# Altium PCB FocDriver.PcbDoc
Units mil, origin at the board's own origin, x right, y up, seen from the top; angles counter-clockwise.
Board outline 2410.04 x 1811.02 mil, 2 copper layers (Top Layer, Bottom Layer); 20 components, 19 nets, 98 pads, 41 vias.
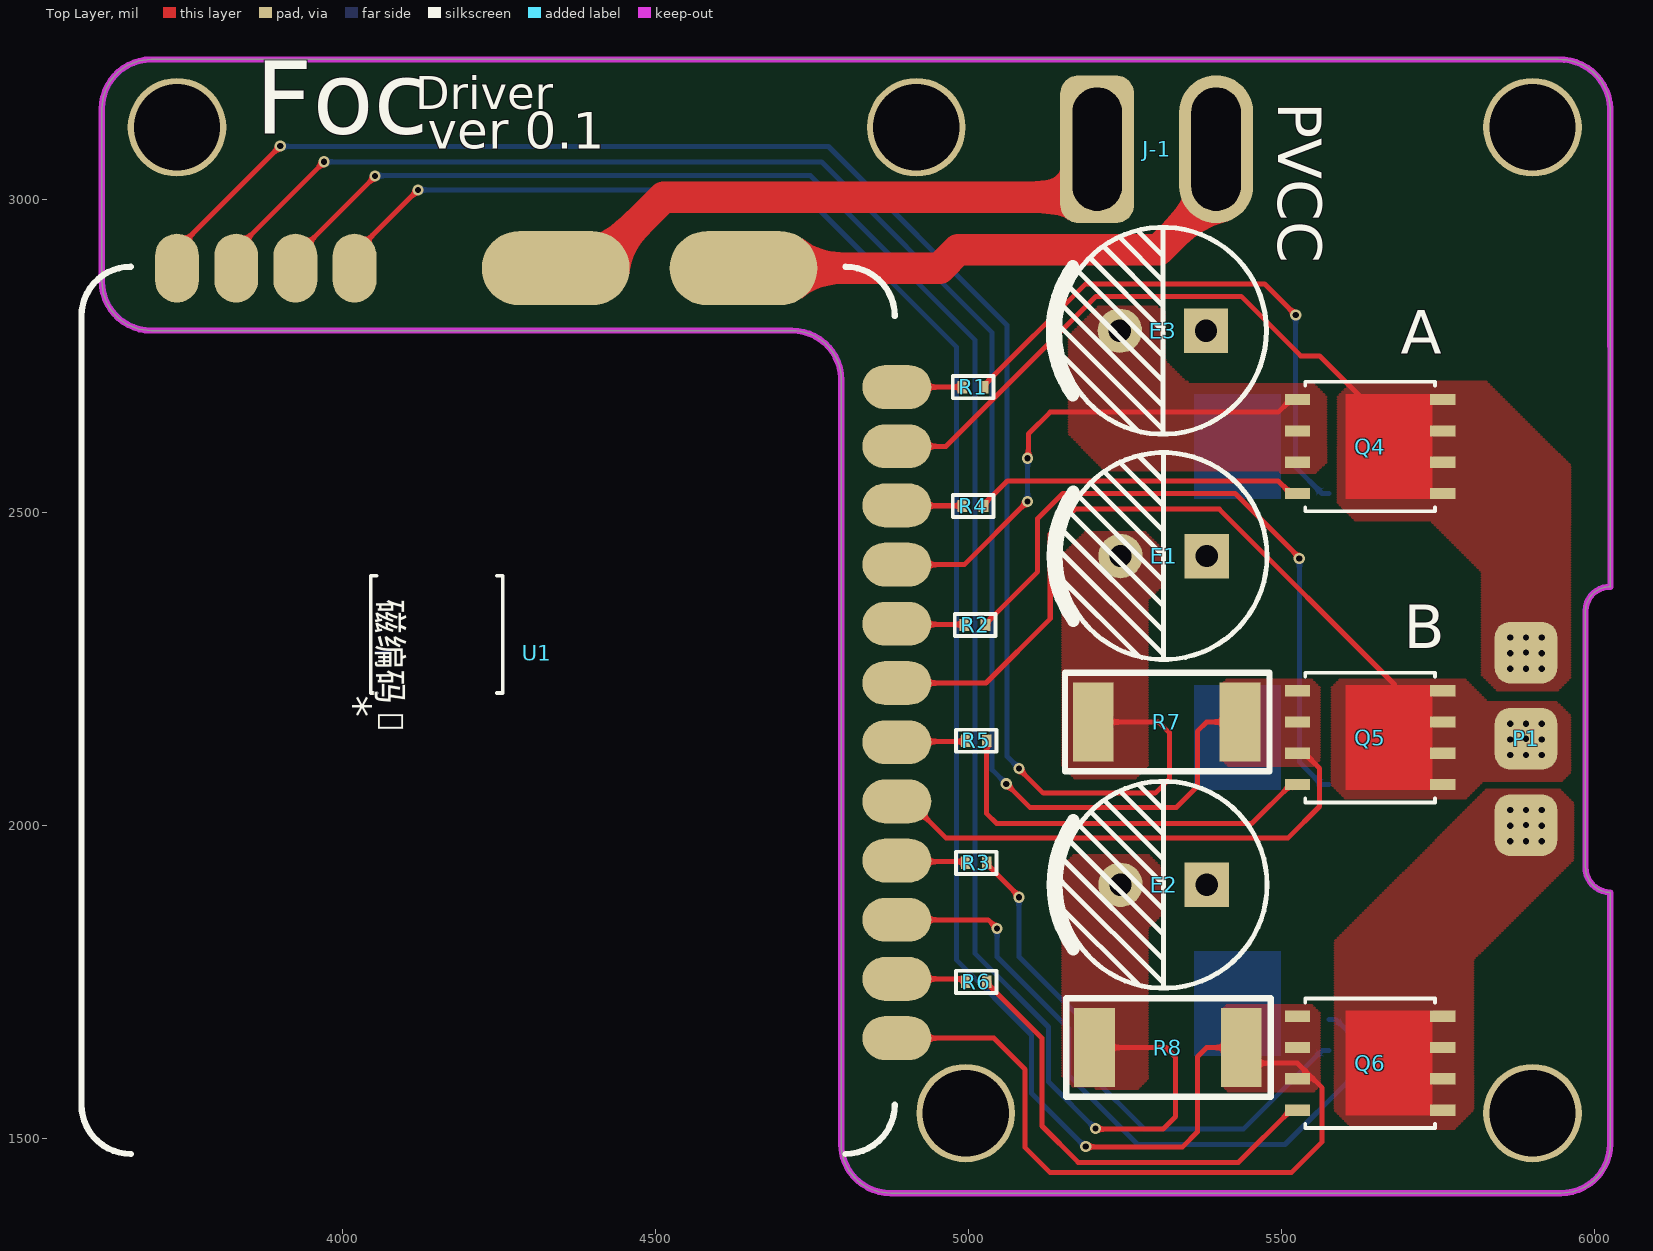
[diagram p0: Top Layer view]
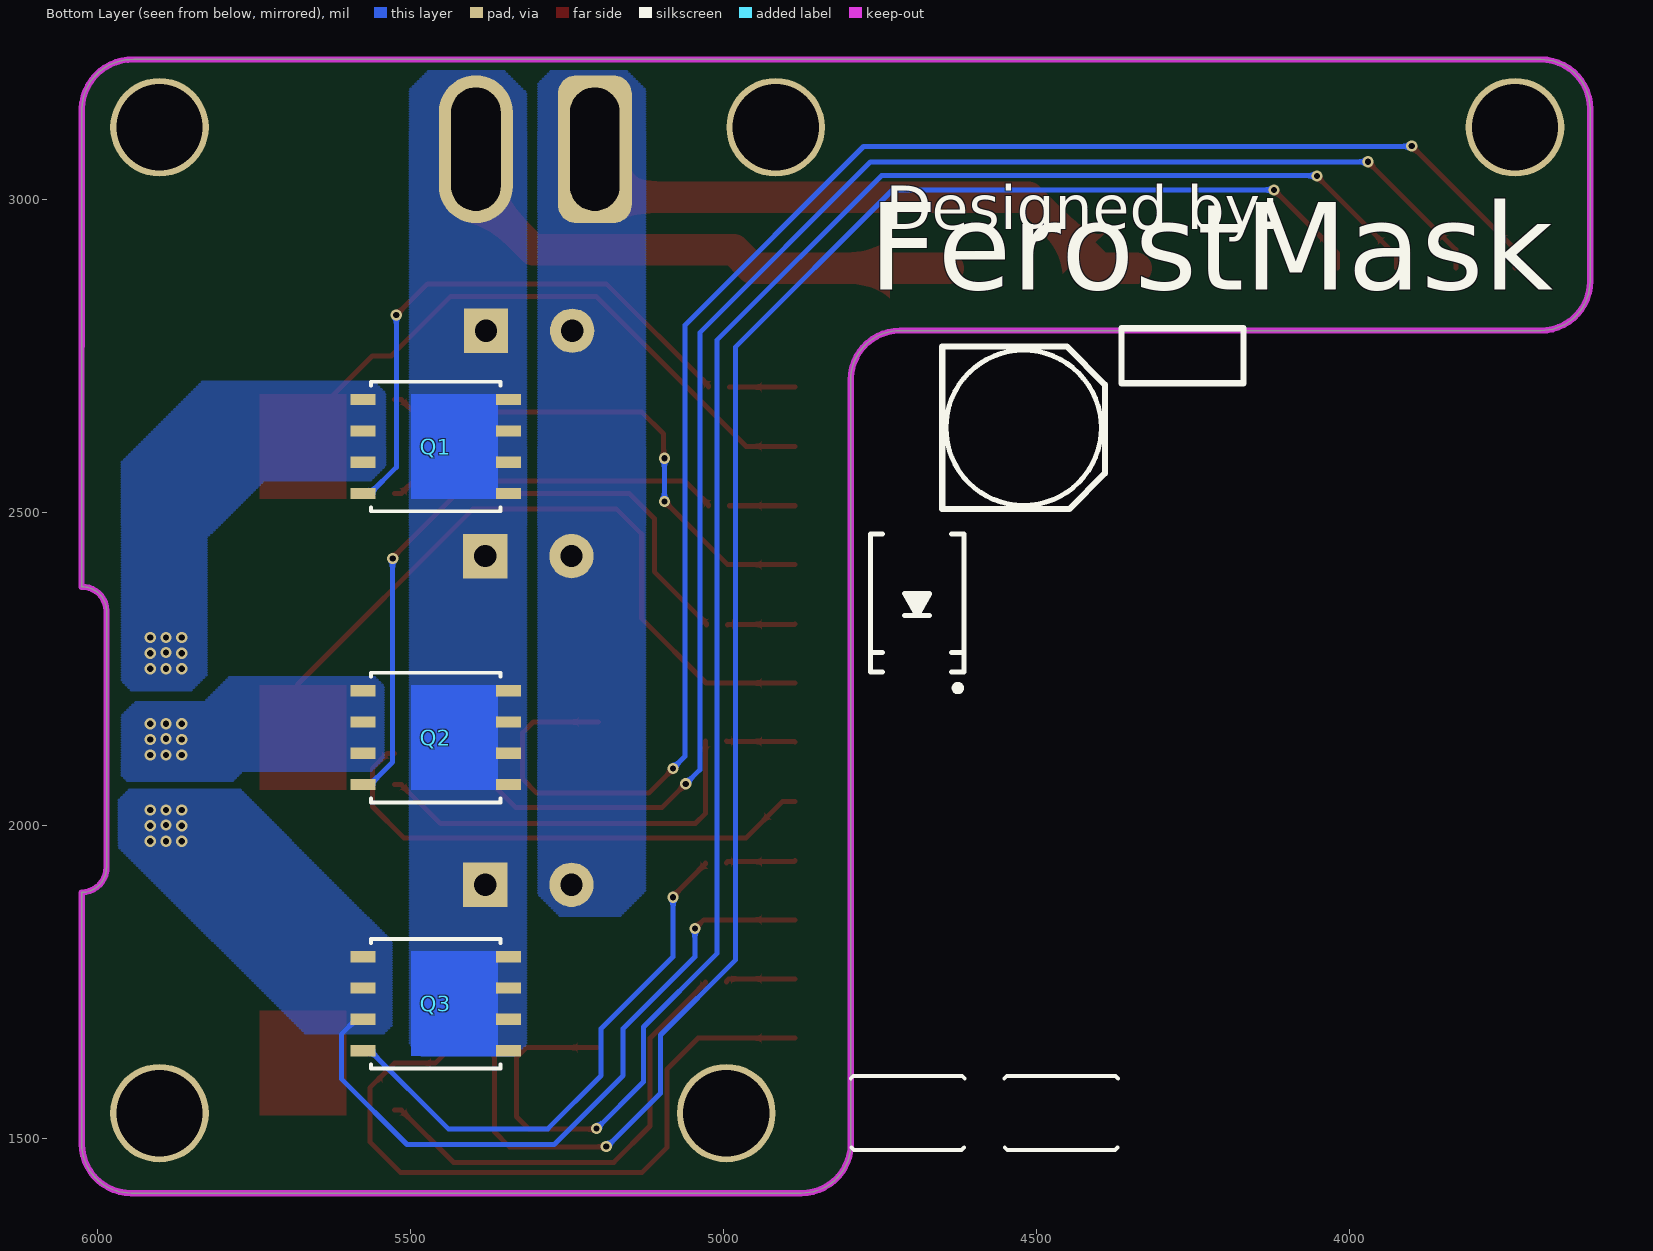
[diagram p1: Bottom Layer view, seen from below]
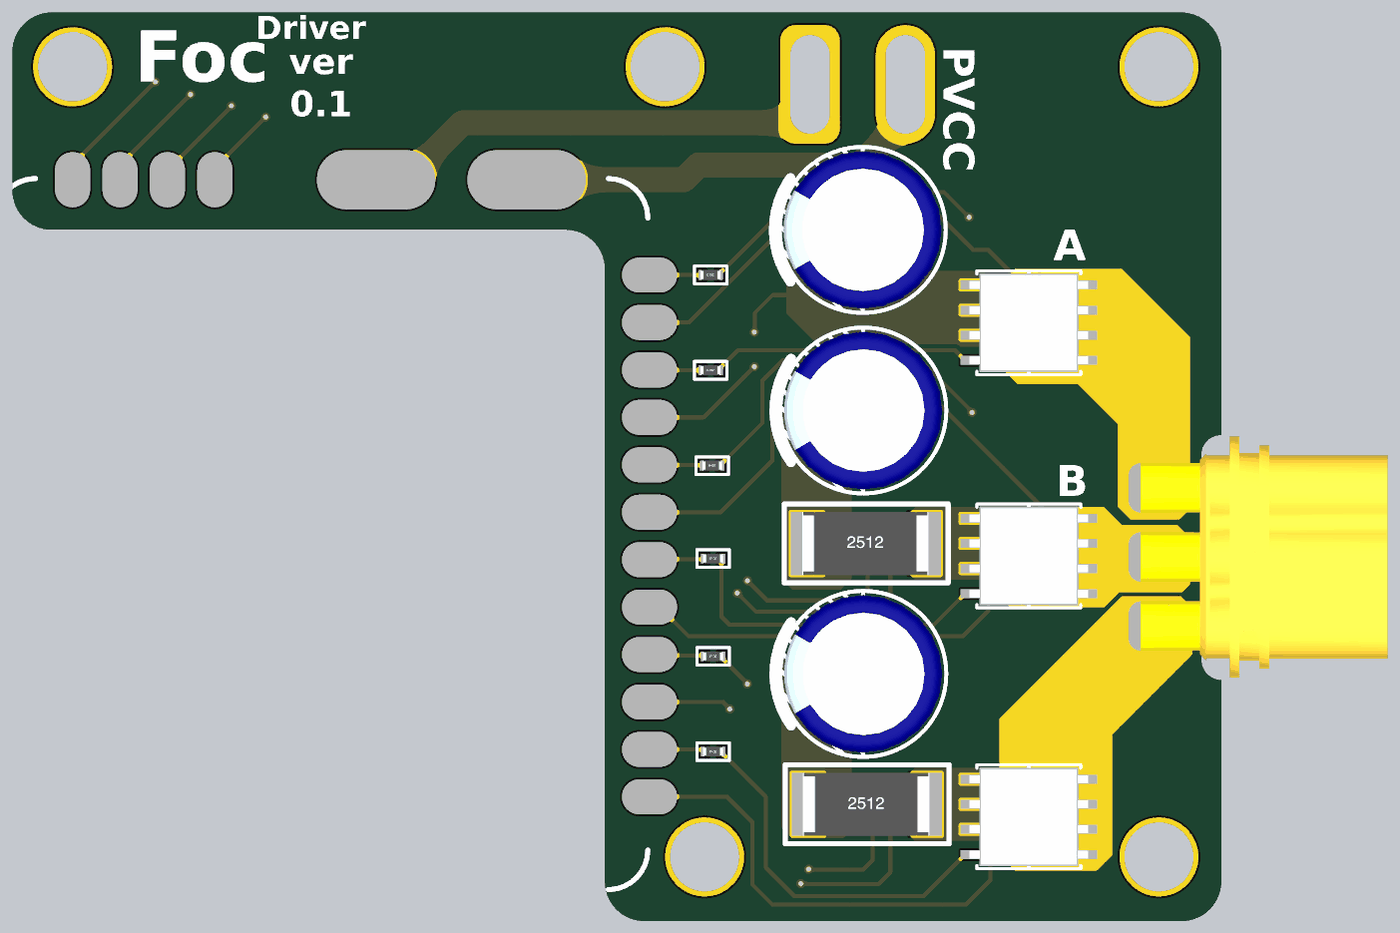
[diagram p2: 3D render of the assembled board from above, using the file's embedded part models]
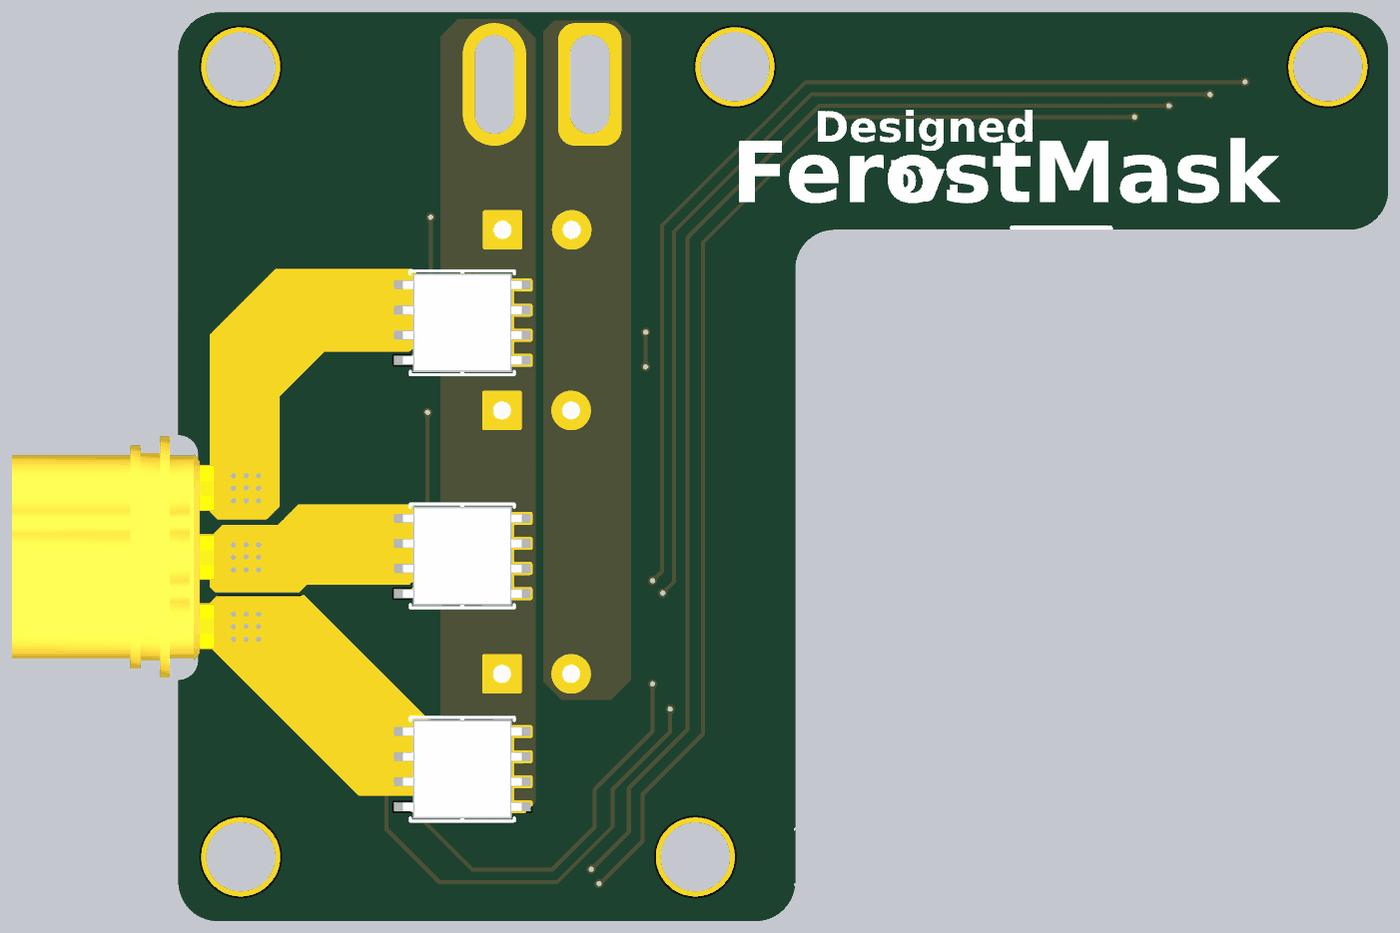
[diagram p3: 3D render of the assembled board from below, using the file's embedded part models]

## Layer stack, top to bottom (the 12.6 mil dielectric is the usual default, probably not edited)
Top Solder: solder mask 0.4, Solder Resist, Dk 3.5
Top Layer: signal copper 1.4
Dielectric 1: dielectric 12.6, FR-4, Dk 4.8
Bottom Layer: signal copper 1.4
Bottom Solder: solder mask 0.4, Solder Resist, Dk 3.5

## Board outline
4717.36,2790.31 cw(c4717.36,2711.57) 4796.1,2711.57 4796.1,1491.1 ccw(c4874.84,1491.1) 4874.84,1412.36 5945.71,1412.36 ccw(c5945.71,1491.1) 6024.45,1491.1 6024.45,1892.68 cw(c6025.22,1932.89) 5985,1933.66 5985,2343.11 cw(c6023.94,2342.01) 6025.04,2380.94 6024.97,2380.95 6024.5,3144.77 ccw(c5943.57,3142.46) 5941.26,3223.39 3693.74,3223.39 ccw(c3693.74,3144.65) 3615,3144.65 3615,2869.06 ccw(c3693.74,2869.06) 3693.74,2790.31

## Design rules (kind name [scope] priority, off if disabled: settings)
Clearance [All] p1: gap=8 ignorepadtopadclearanceinfootprint=TRUE
PlaneConnect [All] p1: planeconnectstyle=Direct reliefexpansion=20 reliefentries=4 reliefconductorwidth=10 reliefairgap=10
PolygonConnect [All] p1: connectstyle=Direct reliefconductorwidth=30 reliefentries=4 polygonreliefangle="90 Angle" airgapwidth=10
RoomDefinition Main [InComponentClass('Main')] p1: confinementstyle=ConfineIn formatcopy=TRUE lockcomponents=FALSE outline 0,0 2000,0 2000,1000 0,1000
RoutingVias [All] p1: holewidth=12 width=24 viastyle="Through Hole" minholewidth=12 minwidth=24 maxholewidth=12 maxwidth=24
SolderMaskExpansion [All] p1: expansion=4 istentingtop=FALSE
Width [All] p1: maxlimit=200 minlimit=6 preferedwidth=6
29 further rules are at their usual default settings.

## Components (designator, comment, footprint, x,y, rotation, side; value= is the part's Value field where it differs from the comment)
E1 "220uF/35V" "CAP 3.5*8*11.5" 5311.1,2430 r180 top
E2 "220uF/35V" "CAP 3.5*8*11.5" 5311.1,1905 r180 top
E3 "220uF/35V" "CAP 3.5*8*11.5" 5310,2790 r180 top
J-1 "Conects" connecter-PWR_vertical 5395,3080 r0 top
P1 "电机接插件-3P" AMASS-MR30-M 5890,2138.11 r90 top
Q1 "2SK3615" "SOP Advance_TOS" 5459,2605 r180 bottom
Q2 "2SK3615" "SOP Advance_TOS" 5459,2140 r180 bottom
Q3 "2SK3615" "SOP Advance_TOS" 5459,1715 r180 bottom
Q4 "2SK3615" "SOP Advance_TOS" 5641,2605 r0 top
Q5 "2SK3615" "SOP Advance_TOS" 5641,2140 r0 top
Q6 "2SK3615" "SOP Advance_TOS" 5641,1620 r0 top
R1 "2.2R" R0402_L 5006.73,2700 r0 top
R2 "2.2R" R0402_L 5010,2320 r0 top
R3 "2.2R" R0402_L 5011.73,1940 r0 top
R4 "2.2R" R0402_L 5006.73,2510 r0 top
R5 "2.2R" R0402_L 5011.73,2135 r0 top
R6 "2.2R" R0402_L 5011.73,1750 r0 top
R7 "0.01R" R2512_L 5315,2165 r0 top
R8 "0.01R" R2512_L 5316.89,1645 r0 top
U1 "FocLogic" FocLogic 4340,2890 r270 top

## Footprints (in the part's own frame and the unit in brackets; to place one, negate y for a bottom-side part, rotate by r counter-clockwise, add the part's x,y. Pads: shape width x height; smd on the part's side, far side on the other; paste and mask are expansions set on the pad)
AMASS-MR30-M [mm]
  rrect50% 2.5x2.54 smd: 1(-3.5,0) 2(0,0) 3(3.5,0)
  body extent -6.1,-11.84 6.1,0.66, height 2.6
"CAP 3.5*8*11.5" [mm] "脚距3.5mm直径8mm高度11.5mm"
  rect 1.8x1.8 hole 0.9: 1(-1.75,0)
  round 1.8 hole 0.9: 2(1.75,0)
  silkscreen extent -4.2,-4.2 4.5,4.2, body extent -4,-4 4.01,4, height 11.53
connecter-PWR_vertical [mm]
  oval 3x6 hole 5 slot 2 at 0 deg: 1(0,0)
  rrect50% 3x6 hole 5 slot 2 at 0 deg: 2(-4.826,0)
FocLogic [mil]
  oval 70x110 smd: 1(1230,545) 2(1135.45,545) 3(1040.91,545) 4(946.36,545) 5(851.82,545) 6(757.27,545) 7(662.73,545) 8(568.18,545) 9(473.64,545) 10(379.09,545) 11(284.55,545)
  oval 70x110 smd mask+4: 12(190,545)
  oval 118.11x236.22 smd: 13(0,300) 14(0,0)
  oval 110x70 smd: 15(0,-321.36) 16(0,-415.91) 17(0,-510.45) 18(0,-605)
  silkscreen extent -2,-758 1415,542
R0402_L [mm] "1/16W贴片电阻"
  rect 0.4x0.5 smd: 1(-0.425,0) 2(0.425,0)
  silkscreen extent -0.82,-0.45 0.83,0.45, body extent -0.5,-0.25 0.5,0.25, height 0.3
R2512_L [mm] "1W贴片电阻            联系卖家 免费查找封装"
  rect 1.65x3.2 smd: 1(-2.95,0) 2(3,0)
  silkscreen extent -4.1,-2 4.2,2, body extent -3.2,-1.6 3.2,1.6, height 0.55
"SOP Advance_TOS" [mil]
  rect 40x18 smd: 1(-116,-75) 2(116,-75) 2(116,-25) 2(116,25) 2(116,75) 3(-116,-25) 3(-116,25) 3(-116,75)
  Top Layer region: -39,83.5 99,83.5 99,-83.5 -39,-83.5
  silkscreen extent -104,-104 104,104, body extent -118,-104 118,104, height 37

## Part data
E1 E2 E3: library part C-CM, "电容"
J-1 P1: "插接件"
Q1 Q2 Q3 Q4 Q5 Q6: library part MOSFETN, "MOSFET"
R1 R2 R3 R4 R5 R6 R7 R8: library part R, "电阻"
U1: "PCBModel"

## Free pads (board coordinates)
  round 157.48 hole 137.8: 8(3735,3115) 8(4916.1,3115) 8(4994.84,1540.2) 8(5900.35,1540.2) 8(5900.35,3115)

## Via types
v1: diameter 18, hole 10, Top Layer to Bottom Layer, tented both sides, 41 vias

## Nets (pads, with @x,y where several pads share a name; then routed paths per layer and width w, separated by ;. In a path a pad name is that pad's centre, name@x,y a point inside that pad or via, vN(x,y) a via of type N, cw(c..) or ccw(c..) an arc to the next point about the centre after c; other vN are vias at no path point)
GH_A: R1.1 U1.12 | length 105
  Top Layer w8: U1.12 R1.1
GH_B: R2.1 U1.8 | length 109
  Top Layer w8: U1.8 4885.91,2320.91 4992.36,2320.91 R2.1
GH_C: R3.1 U1.4 | length 111.5
  Top Layer w8: U1.4 4886.82,1941.82 4993.18,1941.82 R3.1
GL_A: R4.1 U1.10 | length 105.4
  Top Layer w8: U1.10 4885.45,2510.45 4989.55,2510.45 R4.1
GL_B: R5.1 U1.6 | length 110.9
  Top Layer w8: U1.6 4886.14,2133.86 4993.86,2133.86 R5.1
GL_C: R6.1 U1.2 | length 112.3
  Top Layer w8: U1.2 4991.13,1754.55 4995,1750.67 R6.1
GND: E1.2 E2.2 E3.2 J-1.2 Q4.3 R7.1 R8.1 U1.9 U1.14 U1.16 U1.18 | length 7480.3
  Top Layer w8: U1.18 3735,2920 v1(3900,3085) ; U1.16 3924.09,2909.09 v1@4050,3035 ; U1.9 4992.65,2416.36 5093.4,2517.12 v1(5093.83,2517.12) ; v1@5079.76,2090.42 5118.82,2051.35 5297.58,2051.35 5320.2,2073.97 5320.2,2147.92 5303.11,2165 R7.1 ; v1(5093.75,2586.26) 5095,2587.51 5095,2625 5130,2660 5494,2660 5514,2680 Q4.3@5525,2680 ; R8.1 5315,1645 5330,1630 5330,1534.64 5309.99,1514.62 v1@5201.25,1514.62
  Top Layer w50: U1.14 4399.06,2890 4512.31,3003.26 5171.29,3003.26 5205,3036.97 J-1.2
  Bottom Layer w8: v1@3899.98,3084.72 3900.32,3084.38 4775.62,3084.38 5061,2799 5061,2110.1 v1(5080.22,2090.87) ; v1@4051.44,3037.71 4747.15,3037.71 5010,2774.86 5010,1795 5127.3,1677.7 5127.3,1590.21 v1@5202.91,1514.6 ; v1(5093.83,2517.12) 5093.83,2584.99 v1@5094.64,2585.8
  other v1: 5202.2,1515.61 4051.44,3037.38
NetQ1_1: Q1.1 R1.2 | length 902.3
  Top Layer w8: R1.2 5023.46,2701.97 5186.5,2865 5472.31,2865 v1(5522.06,2815.24)
  Bottom Layer w8: v1(5522.06,2815.24) 5522.06,2571.94 5564,2530 Q1.1
NetQ2_1: Q2.1 R2.2 | length 1073.3
  Top Layer w8: R2.2 5026.73,2321.97 5110,2405.24 5110,2490 5150,2530 5425.49,2530 v1@5531.41,2424.08
  Bottom Layer w8: v1(5527.83,2426.01) 5528.15,2425.69 5528.15,2100.85 5564,2065 Q2.1
NetQ3_1: Q3.1 R3.2 | length 876
  Top Layer w8: R3.2 5028.46,1938.03 5080,1886.5 v1(5080,1885)
  Bottom Layer w8: v1(5080,1885) 5080,1790 5195,1675 5195,1600 5280,1515 5439,1515 5564,1640 Q3.1
NetQ4_1: Q4.1 R4.2 | length 527.5
  Top Layer w8: R4.2 5023.46,2511.97 5061.5,2550 5494,2550 5514,2530 Q4.1
NetQ5_1: Q5.1 R5.2 | length 645.3
  Top Layer w8: R5.2 5028.46,2018.55 5044.3,2002.72 5451.72,2002.72 5514,2065 Q5.1
NetQ6_1: Q6.1 R6.2 | length 733.7
  Top Layer w8: R6.2 5028.46,1748.03 5116.69,1659.81 5116.69,1519.66 5174.65,1461.7 5430.7,1461.7 5514,1545 Q6.1
SH_A: P1.3 Q1.3 Q4.2 U1.11 | length 960
  Top Layer w8: U1.11 4963.61,2605.45 5203.15,2845 5435,2845 5530,2750 5560,2750 5660,2650 5665,2650
  other v1: 5865,2250 5890,2250 5915,2250 5865,2275 5915,2275 5890,2275.91 5865,2300 5890,2300 5915,2300
SH_B: P1.2 Q2.3 Q5.2 U1.7 | length 1190.1
  Top Layer w8: U1.7 5027.27,2227.27 5130,2330 5130,2465 5170,2505 5400,2505 5680,2225 5680,2140
  other v1: 5865,2112.2 5890,2112.2 5915,2112.2 5865,2137.2 5915,2137.2 5890,2138.11 5865,2162.2 5890,2162.2 5915,2162.2
SH_C: P1.1 Q3.3 Q6.2 U1.3 | length 1103.5
  Top Layer w8: U1.3 5030.91,1849.09 v1(5045,1835)
  Bottom Layer w8: v1(5045,1835) 5045,1790 5160,1675 5160,1600 5270,1490 5505,1490 5610,1595 5610,1666 5586,1690 Q3.3@5575,1690
  other v1: 5865,1974.41 5890,1974.41 5915,1974.41 5865,1999.41 5915,1999.41 5890,2000.31 5865,2024.41 5890,2024.41 5915,2024.41
SL_B: Q5.3 R7.2 U1.5 U1.17 | length 3462.9
  Top Layer w8: U1.17 3829.55,2919.55 v1(3970,3060) ; U1.5 4905,2038.18 4963.18,1980 5510,1980 5560,2030 5560,2091 5536,2115 Q5.3@5525,2115 ; v1@5058.76,2067.36 5097.47,2028.65 5331.69,2028.65 5365,2061.96 5365,2150 5380,2165 R7.2
  Bottom Layer w8: v1@3970,3059.82 4764.46,3059.82 5037.3,2786.98 5037.3,2088.7 5059.09,2066.9 v1(5059.85,2066.15)
SL_C: Q6.3 R8.2 U1.1 U1.15 | length 3987.2
  Top Layer w8: U1.15 4018.64,2913.64 v1(4120,3015) ; U1.1 5040,1660 5090,1610 5090,1485 5130,1445 5515,1445 5564.33,1494.33 5564.33,1580.67 5543,1602 5525,1620 5460,1620 R8.2 5380,1645 5365,1630 5365,1510 5341.42,1486.42 v1@5185.41,1486.42
  Bottom Layer w8: v1@4119.23,3014.91 4729.39,3014.91 4980,2764.3 4980,1785 5100,1665 5100,1571.84 v1@5187.36,1484.48
  other v1: 5186.64,1486.83
VCC: E1.1 E2.1 E3.1 J-1.1 Q1.2 Q2.2 Q3.2 U1.13 | length 874.2
  Top Layer w50: U1.13 4953.31,2890 4982.63,2919.32 5303.53,2919.32 5395,3010.79 J-1.1

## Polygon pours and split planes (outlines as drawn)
SH_C on Bottom Layer "NONET_L01_P-001" (hatched Horizontal grid 4 track 5, remove dead copper, pour order 10): 5775,2060 5550,1835 5530,1815 5530,1680 5545,1665 5665,1665 5795,1795 5965,1965 5965,2040 5945,2060
SH_B on Bottom Layer "NONET_L01_P-001" (hatched Horizontal grid 4 track 5, remove dead copper, pour order 9): 5560,2240 5540,2220 5540,2105 5560,2085 5770,2085 5785,2070 5950,2070 5960,2080 5960,2175 5935,2200 5825,2200 5785,2240
SH_A on Bottom Layer "NONET_L01_P-001" (hatched Horizontal grid 4 track 5, remove dead copper, pour order 8): 5560,2710 5540,2690 5540,2575 5565,2550 5735,2550 5825,2460 5825,2240 5850,2215 5945,2215 5960,2230 5960,2580 5830,2710
GND on Bottom Layer "NONET_L01_P-001" (hatched Horizontal grid 4 track 5, remove dead copper, pour order 1): 5275,3205 5295,3185 5295,1890 5260,1855 5165,1855 5125,1895 5125,3175 5155,3205
VCC on Bottom Layer "NONET_L01_P-001" (hatched Horizontal grid 4 track 5, remove dead copper, pour order 0): 5355,3210 5315,3170 5315,1650 5335,1630 5480,1630 5500,1650 5500,3175 5465,3210
SL_C on Top Layer "NONET_L01_P-001" (hatched Horizontal grid 4 track 5, remove dead copper, pour order 12): 5545,1715 5560,1700 5560,1585 5550,1575 5415,1575 5405,1585 5405,1705 5415,1715
SL_B on Top Layer "NONET_L01_P-001" (hatched Horizontal grid 4 track 5, remove dead copper, pour order 11): 5545,2235 5560,2220 5560,2105 5550,2095 5415,2095 5405,2105 5405,2225 5415,2235
SH_C on Top Layer "NONET_L01_P-001" (hatched Horizontal grid 4 track 5, remove dead copper, pour order 7): 5775,1515 5805,1545 5805,1785 5945,1925 5965,1945 5965,2035 5940,2060 5830,2060 5585,1815 5585,1545 5615,1515
SH_B on Top Layer "NONET_L01_P-001" (hatched Horizontal grid 4 track 5, remove dead copper, pour order 6): 5595,2235 5580,2220 5580,2065 5605,2040 5790,2040 5820,2070 5945,2070 5960,2085 5960,2175 5935,2200 5825,2200 5790,2235
SH_A on Top Layer "NONET_L01_P-001" (hatched Horizontal grid 4 track 5, remove dead copper, pour order 5): 5615,2710 5590,2685 5590,2515 5620,2485 5740,2485 5820,2405 5820,2240 5845,2215 5940,2215 5960,2235 5960,2575 5825,2710
GND on Top Layer "NONET_L01_P-001" (hatched Horizontal grid 4 track 5, remove dead copper, pour order 4): 5215,2840 5282.95,2840 5312.5,2820 5312.5,2745 5314.7,2739.7 5344.69,2709.7 5350,2707.5 5550,2705 5570,2685 5570,2580 5550,2560 5225,2560 5160,2625 5160,2785
GND on Top Layer "NONET_L01_P-001" (hatched Horizontal grid 4 track 5, remove dead copper, pour order 3): 5170,1955 5150,1935 5150,1600 5170,1580 5270,1580 5285,1595 5285,1835 5305,1855 5305,1935 5285,1955
GND on Top Layer "NONET_L01_P-001" (hatched Horizontal grid 4 track 5, remove dead copper, pour order 2): 5187.87,2470 5150,2432.13 5150,2095 5170,2075 5265,2075 5285,2095 5285,2360 5305,2380 5305,2445 5280,2470
no net on Bottom Solder "NONET_L01_P-001" (hatched Horizontal grid 4 track 5, remove dead copper): 5775,2060 5550,1835 5530,1815 5530,1680 5545,1665 5665,1665 5795,1795 5965,1965 5965,2040 5945,2060
no net on Bottom Solder "NONET_L01_P-001" (hatched Horizontal grid 4 track 5, remove dead copper): 5560,2240 5540,2220 5540,2105 5560,2085 5770,2085 5785,2070 5950,2070 5960,2080 5960,2175 5935,2200 5825,2200 5785,2240
no net on Bottom Solder "NONET_L01_P-001" (hatched Horizontal grid 4 track 5, remove dead copper): 5560,2710 5540,2690 5540,2575 5565,2550 5735,2550 5825,2460 5825,2240 5850,2215 5945,2215 5960,2230 5960,2580 5830,2710
no net on Top Solder "NONET_L01_P-001" (hatched Horizontal grid 4 track 5, remove dead copper): 5775,1515 5805,1545 5805,1785 5945,1925 5965,1945 5965,2035 5940,2060 5830,2060 5585,1815 5585,1545 5615,1515
no net on Top Solder "NONET_L01_P-001" (hatched Horizontal grid 4 track 5, remove dead copper): 5595,2235 5580,2220 5580,2065 5605,2040 5790,2040 5820,2070 5945,2070 5960,2085 5960,2175 5935,2200 5825,2200 5790,2235
no net on Top Solder "NONET_L01_P-001" (hatched Horizontal grid 4 track 5, remove dead copper): 5615,2710 5590,2685 5590,2515 5620,2485 5740,2485 5820,2405 5820,2240 5845,2215 5940,2215 5960,2235 5960,2575 5825,2710

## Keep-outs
Keep-Out Layer:
  the board outline again, w10

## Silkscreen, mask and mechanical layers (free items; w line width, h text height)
Top Overlay:
  text "PVCC" at 5471,3155 h120 r270
  text "Driver" at 4115.47,3126.38 h90
  text "Foc" at 3860,3066.05 h200
  text "ver 0.1" at 4135.47,3061.38 h100
  text "A" at 5690,2730 h120
  text "B" at 5695,2260 h120
Bottom Overlay:
  text "Designed by:" at 4739.87,2929.36 h120
  text "FerostMask" at 4767.37,2809.36 h240
Mechanical 1:
  the board outline again, w10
